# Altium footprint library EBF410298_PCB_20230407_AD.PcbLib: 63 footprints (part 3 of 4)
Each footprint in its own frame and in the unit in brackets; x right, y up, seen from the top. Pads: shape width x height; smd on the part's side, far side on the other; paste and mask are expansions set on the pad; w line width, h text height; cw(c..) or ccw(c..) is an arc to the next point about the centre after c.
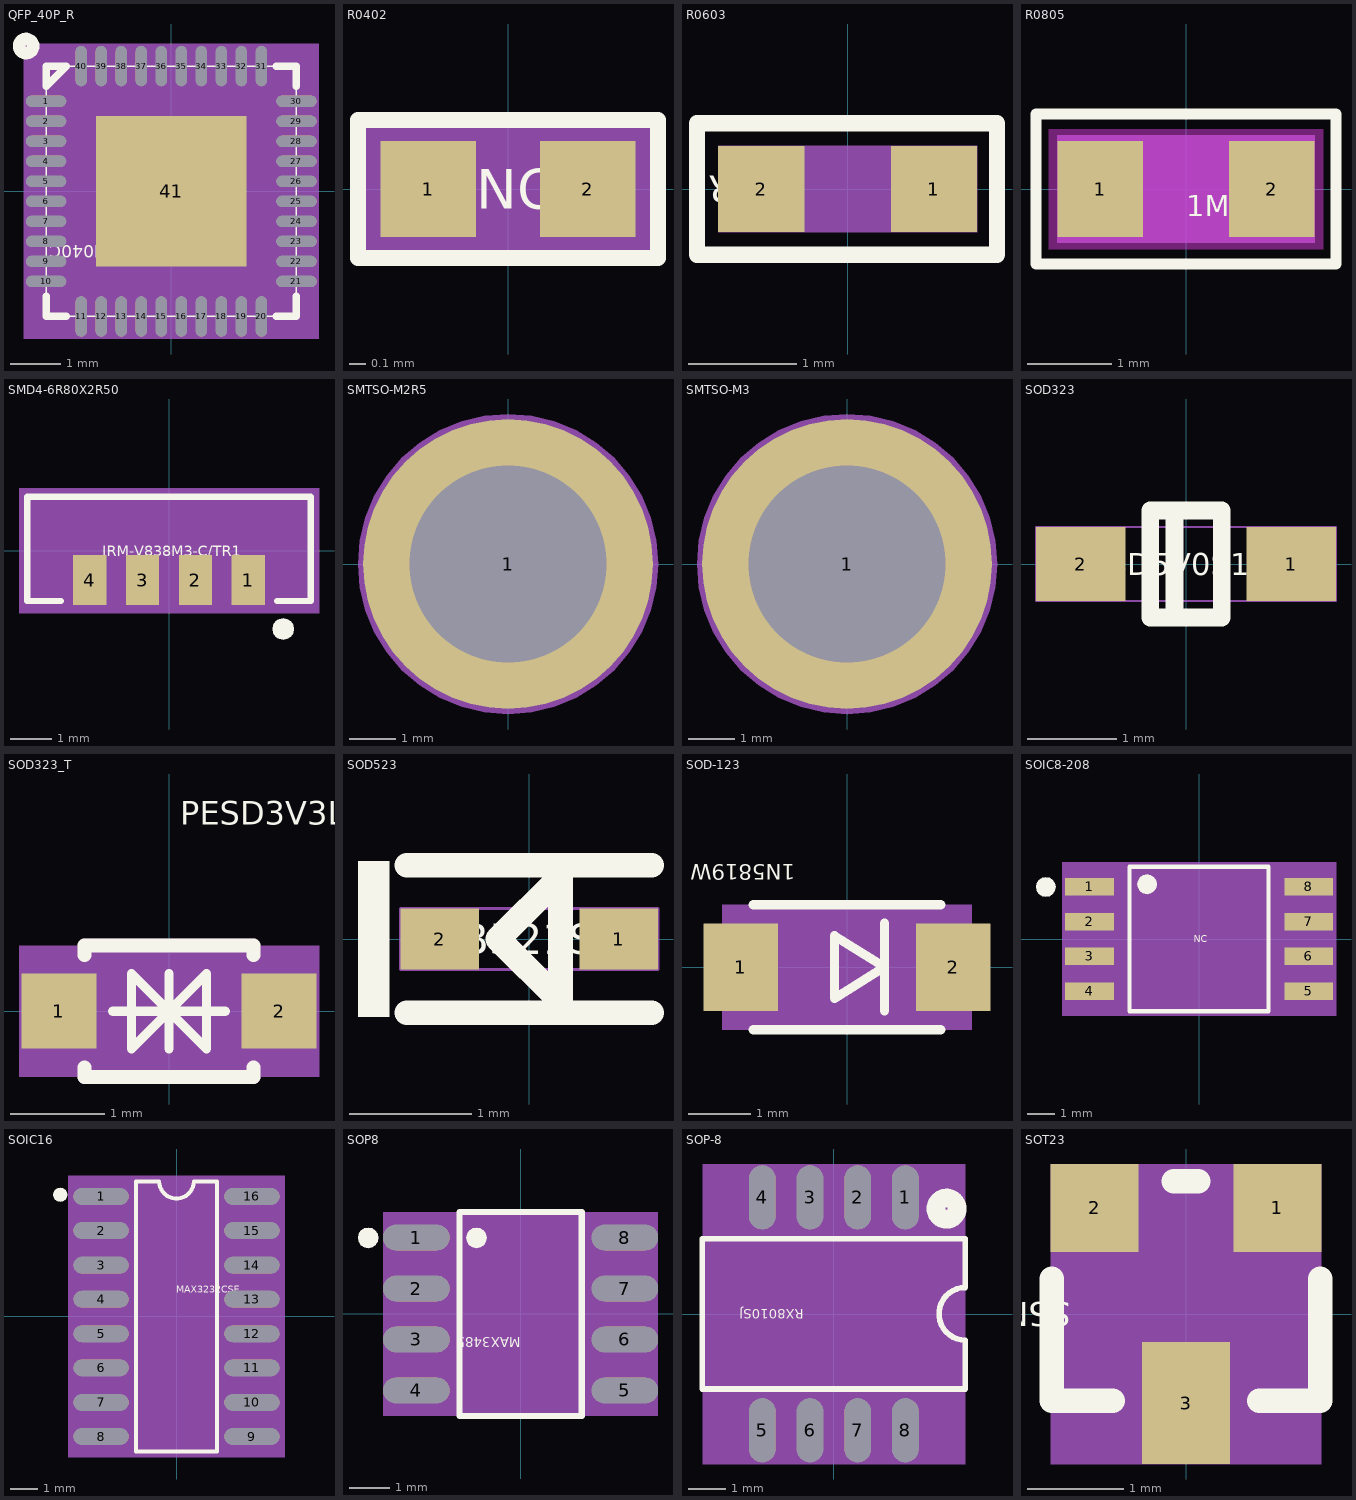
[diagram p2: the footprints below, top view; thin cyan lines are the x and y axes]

## QFP_40P_R [mil] "QFP_40P_R"
pads (41):
  oval 31.5x8.66 smd: 1(-98.43,70.87) 2(-98.43,55.12) 3(-98.43,39.37) 4(-98.43,23.62) 5(-98.43,7.87) 6(-98.43,-7.87) 7(-98.43,-23.62) 8(-98.43,-39.37) 9(-98.43,-55.12) 10(-98.43,-70.87) 21(98.43,-70.87) 22(98.43,-55.12) 23(98.43,-39.37) 24(98.43,-23.62) 25(98.43,-7.87) 26(98.43,7.87) 27(98.43,23.62) 28(98.43,39.37) 29(98.43,55.12) 30(98.43,70.87)
  oval 8.66x31.5 smd: 11(-70.87,-98.43) 12(-55.12,-98.43) 13(-39.37,-98.43) 14(-23.62,-98.43) 15(-7.87,-98.43) 16(7.87,-98.43) 17(23.62,-98.43) 18(39.37,-98.43) 19(55.12,-98.43) 20(70.87,-98.43) 31(70.87,98.43) 32(55.12,98.43) 33(39.37,98.43) 34(23.62,98.43) 35(7.87,98.43) 36(-7.87,98.43) 37(-23.62,98.43) 38(-39.37,98.43) 39(-55.12,98.43) 40(-70.87,98.43)
  rect 118.11x118.11 smd: 41(0,0)
Top Overlay:
  circle w9.84: c-114.17,114.17 r5.56
  lines w1: -98.43,-98.43 98.43,-98.43 98.43,98.43 -98.43,98.43 -98.43,-98.43
  lines w5.91: -98.43,-82.68 -98.43,-98.43 -82.68,-98.43 ; 82.68,-98.43 98.43,-98.43 98.43,-82.68 ; 82.68,98.43 98.43,98.43 98.43,82.68 ; -98.43,82.68 -98.43,98.43 -82.68,98.43 -98.43,82.68
  text "JL2101-N040C" at 0,-42.31 h9.84
Mechanical 5:
  dashed: -116.14,-116.14 116.14,-116.14 116.14,116.14 -116.14,116.14
Top 3D Body:
  region: -116.14,-116.14 116.14,-116.14 116.14,116.14 -116.14,116.14
Mechanical 17:
  text "12" at -55.12,-114.43 h20
  text "26" at 98.43,-8.13 h20
  text "27" at 98.43,7.62 h20
  text "22" at 98.43,-71.12 h20
  text "23" at 98.43,-55.37 h20
  text "24" at 98.43,-39.62 h20
  text "39" at -55.12,82.43 h20
  text "25" at 98.43,-23.87 h20
  text "40" at -70.87,82.43 h20
  text "11" at -70.87,-114.43 h20
  text "21" at 98.43,-86.87 h20
  text "8" at -98.43,-47.37 h20
  text "3" at -98.43,31.37 h20
  text "38" at -39.37,82.43 h20
  text "35" at 7.87,82.43 h20
  text "30" at 98.43,54.87 h20
  text "14" at -23.62,-114.43 h20
  text "20" at 70.87,-114.43 h20
  text "13" at -39.37,-114.43 h20
  text "34" at 23.62,82.43 h20
  text "33" at 39.37,82.43 h20
  text "10" at -98.43,-86.87 h20
  text "9" at -98.43,-63.12 h20
  text "7" at -98.43,-31.62 h20
  text "6" at -98.43,-15.87 h20
  text "5" at -98.43,-0.13 h20
  text "4" at -98.43,15.62 h20
  text "2" at -98.43,47.12 h20
  text "1" at -98.43,62.87 h20
  text "41" at 0,-16 h20
  text "32" at 55.12,82.43 h20
  text "29" at 98.43,39.12 h20
  text "37" at -23.62,82.43 h20
  text "36" at -7.87,82.43 h20
  text "31" at 70.87,82.43 h20
  text "19" at 55.12,-114.43 h20
  text "15" at -7.87,-114.43 h20
  text "16" at 7.87,-114.43 h20
  text "17" at 23.62,-114.43 h20
  text "18" at 39.37,-114.43 h20
  text "28" at 98.43,23.37 h20
Top Assembly:
  lines w1: -98.43,90.55 -90.55,98.43 ; -98.43,-98.43 98.43,-98.43 98.43,98.43 -98.43,98.43 -98.43,-98.43
  text ".Designator" at 0,-60 h50
3D body: height 150, standoff 0, extent -116.14,-116.14 116.14,116.14

## R0402 [mm] "R0402"
pads (2):
  rect 0.599x0.599 smd: 1(-0.5,0) 2(0.5,0)
Top Overlay:
  lines w0.102: -0.94,-0.432 0.94,-0.432 0.94,0.432 -0.94,0.432 -0.94,-0.432
  text "NC" at -0.2,-0.125 h0.25
Top 3D Body:
  region: 0.94,0.432 0.94,-0.432 -0.94,-0.432 -0.94,0.432
Mechanical 17:
  text "2" at 0.246,0 h0.64
  text "1" at -0.754,0 h0.64
Top Assembly:
  dashed: -0.94,-0.432 -0.94,0.432 0.94,0.432 0.94,-0.432
3D body: height 3.81, standoff 0, extent -0.94,-0.432 0.94,0.432

## R0603 [mil] "R0603"
pads (2):
  rect 31.5x31.5 smd: 1(31.5,0) 2(-31.5,0)
Top Overlay:
  lines w6: -55,-24 54.5,-24 54.5,24 -55,24 -55,-24
  text "510R" at -15.74,4.92 h9.84
Top 3D Body:
  region: 47.24,15.75 47.24,-15.75 -47.24,-15.75 -47.24,15.75
Mechanical 17:
  text "1" at 13.5,0 h45
  text "2" at -49.5,0 h45
3D body: height 150, standoff 0, extent -47.24,-15.75 47.24,15.75

## R0805 [mil] "R0805"
pads (2):
  rect 40x45 smd: 1(-40,0) 2(40,0)
Top Overlay:
  lines w5: -70,-35 70,-35 70,35 -70,35 -70,-35
  text "1M" at 0.01,-12.79 h9.84
Top 3D Body:
  region: -60,25 60,25 60,-25 -60,-25
Multi-Layer keep-out:
  region: -64,-28 -64,28 64,28 64,-28
Mechanical 17:
  text "1" at -40,-12 h30
  text "2" at 40,-12 h30
Top Assembly:
  text "R0805" at -115,45 h25
3D body: height 150, standoff 0, extent -60,-25 60,25

## SMD4-6R80X2R50 [mm] "SMD4-6R80X2R50"
pads (4):
  rect 0.8x1.2 smd: 1(1.905,-0.7) 2(0.635,-0.7) 3(-0.635,-0.7) 4(-1.905,-0.7)
Top Overlay:
  dashed: 2.996,-1.875 2.976,-1.777 2.921,-1.695 2.839,-1.639 2.741,-1.62 2.643,-1.639 2.616,-1.658 2.561,-1.695 2.505,-1.777 2.486,-1.875 2.505,-1.973 2.561,-2.055 2.616,-2.092 2.643,-2.111 2.741,-2.13 2.839,-2.111 2.921,-2.055 2.976,-1.973
  lines w0.15: -2.6,-1.2 -3.4,-1.2 -3.4,1.3 3.4,1.3 3.4,-1.2 2.6,-1.2
  text "IRM-V838M3-C/TR1" at -1.599,-0.125 h0.25
Top 3D Body:
  region: -3.6,1.5 -3.6,-1.5 3.6,-1.5 3.6,1.5
Mechanical 17:
  text "4" at -2.159,-0.7 h0.64
  text "1" at 1.651,-0.7 h0.64
  text "2" at 0.381,-0.7 h0.64
  text "3" at -0.889,-0.7 h0.64
Top Assembly:
  lines w0.15: -3.4,-1.2 3.4,-1.2 3.4,1.3 -3.4,1.3 -3.4,-1.2
3D body: height 3.81, standoff 0, extent -3.6,-1.5 3.6,1.5

## SMTSO-M2R5 [mm] "SMTSO-M2R5"
pads (1):
  round 6.2 / inner round 5.2 / far side round 5.2 hole 4.22: 1(0,0)
Top Overlay:
  text "M2.5X3mm" at -0.8,-0.125 h0.25
Top 3D Body:
  region: 3.21,0 3.17,0.502 3.053,0.992 2.86,1.457 2.597,1.887 2.27,2.27 1.887,2.597 1.457,2.86 0.992,3.053 0.502,3.17 0,3.21 -0.502,3.17 -0.992,3.053 -1.457,2.86 -1.601,2.772 -1.887,2.597 -2.27,2.27 -2.597,1.887 -2.86,1.457 -3.053,0.992 -3.17,0.502 -3.21,0 -3.17,-0.502 -3.053,-0.992 -2.86,-1.457 -2.597,-1.887 -2.27,-2.27 -1.887,-2.597 -1.601,-2.772 -1.457,-2.86 -0.992,-3.053 -0.502,-3.17 0,-3.21 0.502,-3.17 0.992,-3.053 1.457,-2.86 1.887,-2.597 2.27,-2.27 2.597,-1.887 2.86,-1.457 3.053,-0.992 3.17,-0.502
Mechanical 17:
  text "1" at -0.254,0 h0.64
3D body: height 3.81, standoff 0, extent -3.21,-3.21 3.21,3.21

## SMTSO-M3 [mm] "SMTSO-M3"
pads (1):
  round 6.2 / inner round 5.2 / far side round 5.2 hole 4.22: 1(0,0)
Top Overlay:
  text "M3X3.5mm" at -0.8,-0.125 h0.25
Top 3D Body:
  region: 3.21,0 3.17,0.502 3.053,0.992 2.86,1.457 2.597,1.887 2.27,2.27 1.887,2.597 1.457,2.86 0.992,3.053 0.502,3.17 0,3.21 -0.502,3.17 -0.992,3.053 -1.457,2.86 -1.601,2.772 -1.887,2.597 -2.27,2.27 -2.597,1.887 -2.86,1.457 -3.053,0.992 -3.17,0.502 -3.21,0 -3.17,-0.502 -3.053,-0.992 -2.86,-1.457 -2.597,-1.887 -2.27,-2.27 -1.887,-2.597 -1.601,-2.772 -1.457,-2.86 -0.992,-3.053 -0.502,-3.17 0,-3.21 0.502,-3.17 0.992,-3.053 1.457,-2.86 1.887,-2.597 2.27,-2.27 2.597,-1.887 2.86,-1.457 3.053,-0.992 3.17,-0.502
Mechanical 17:
  text "1" at -0.376,0 h0.94
3D body: height 3.81, standoff 0, extent -3.21,-3.21 3.21,3.21

## SOD323 [mm] "SOD323"
pads (2):
  rect 1x0.83 smd: 1(1.18,0) 2(-1.18,0)
Top Overlay:
  lines w0.2: -0.13,-0.6 -0.13,0.6 ; -0.4,-0.6 0.4,-0.6 0.4,0.6 -0.4,0.6 -0.4,-0.6
  text "PESD5V0S1BA-N" at -1.3,-0.125 h0.25
Top 3D Body:
  lines w0.025: -1.68,-0.415 -1.68,0.415 1.68,0.415 1.68,-0.415 -1.68,-0.415
Mechanical 17:
  text "2" at -1.302,0 h0.3
  text "1" at 1.058,0 h0.3

## SOD323_T [mm] "SOD323_T"
pads (2):
  rect 0.8x0.8 smd: 1(-1.175,0) 2(1.175,0)
Top Overlay:
  lines w0.1: -0.6,0 0.6,0 ; 0,-0.4 0,0.4 ; 0,0 -0.4,-0.4 -0.4,0.4 0,0 ; 0,0 0.4,0.4 0.4,-0.4 0,0
  lines w0.15: -0.9,-0.6 -0.9,-0.7 0.9,-0.7 0.9,-0.6 ; -0.9,0.6 -0.9,0.7 0.9,0.7 0.9,0.6
  text "PESD3V3L1BA" at 0.122,1.991 h0.25
Top 3D Body:
  region: -1.6,0.7 -1.6,-0.7 1.6,-0.7 1.6,0.7
Mechanical 17:
  text "2" at 1.175,0.254 h0.64
  text "1" at -1.175,0.254 h0.64
Top Assembly:
  lines w0.15: -0.9,-0.7 0.9,-0.7 0.9,0.7 -0.9,0.7 -0.9,-0.7
3D body: height 3.81, standoff 0, extent -1.6,-0.7 1.6,0.7

## SOD523 [mm] "SOD523"
pads (2):
  rect 0.64x0.5 smd: 1(0.73,0) 2(-0.73,0)
Top Overlay:
  dashed: -1.397,0.635 -1.397,-0.635 -1.143,-0.635 -1.143,0.635
  lines w0.2: -1,-0.6 1,-0.6 ; -1,0.6 1,0.6
  lines w0.203: -0.254,0 0.254,0.508 0.254,-0.508 -0.254,0
  text "RB521S30" at -0.8,-0.125 h0.25
Top 3D Body:
  lines w0.025: -1.05,-0.25 1.05,-0.25 1.05,0.25 -1.05,0.25 -1.05,-0.25
Mechanical 17:
  text "1" at 0.273,0 h1.14
  text "2" at -1.187,0 h1.14

## SOD-123 [mm] "SOD-123"
pads (2):
  rect 1.2x1.4 smd: 1(-1.7,0) 2(1.7,0)
Top Overlay:
  lines w0.15: -1.5,-1 1.5,-1 ; -1.5,1 1.5,1 ; 0.6,-0.7 0.6,0.7 ; -0.2,-0.5 -0.2,0.5 0.6,0 -0.2,-0.5
  text "1N5819W" at -0.827,1.649 h0.25
Top 3D Body:
  region: -2,-1 -2,1 2,1 2,-1
Mechanical 17:
  text "2" at 1.385,0 h0.79
  text "1" at -2.015,0 h0.79
3D body: height 3.81, standoff 0, extent -2,-1 2,1

## SOIC8-208 [mm] "SOIC8-208"
pads (8):
  rect 1.778x0.635 smd: 1(-4,1.905) 2(-4,0.635) 3(-4,-0.635) 4(-4,-1.905) 5(4,-1.905) 6(4,-0.635) 7(4,0.635) 8(4,1.905)
Top Overlay:
  dashed: -5.243,1.9 -5.27,2.037 -5.348,2.152 -5.463,2.23 -5.6,2.257 -5.737,2.23 -5.775,2.204 -5.852,2.152 -5.93,2.037 -5.957,1.9 -5.93,1.763 -5.852,1.648 -5.775,1.596 -5.737,1.57 -5.6,1.543 -5.463,1.57 -5.348,1.648 -5.27,1.763
  dashed: -1.543,2 -1.57,2.137 -1.648,2.252 -1.763,2.33 -1.9,2.357 -2.037,2.33 -2.075,2.304 -2.152,2.252 -2.23,2.137 -2.257,2 -2.23,1.863 -2.152,1.748 -2.075,1.696 -2.037,1.67 -1.9,1.643 -1.763,1.67 -1.648,1.748 -1.57,1.863
  lines w0.152: -2.54,-2.64 2.54,-2.64 2.54,2.64 -2.54,2.64 -2.54,-2.64
  text "NC" at -0.2,-0.125 h0.25
Top 3D Body:
  region: -5,2.8 -5,-2.8 5,-2.8 5,2.8
Mechanical 17:
  text "4" at -4.203,-1.905 h0.51
  text "8" at 3.797,1.905 h0.51
  text "7" at 3.797,0.635 h0.51
  text "5" at 3.797,-1.905 h0.51
  text "2" at -4.203,0.635 h0.51
  text "1" at -4.203,1.905 h0.51
  text "6" at 3.797,-0.635 h0.51
  text "3" at -4.203,-0.635 h0.51
Top Assembly:
  lines w0.152: -2.54,-2.64 2.54,-2.64 2.54,2.64 -2.54,2.64 -2.54,-2.64
3D body: height 3.81, standoff 0, extent -5,-2.8 5,2.8

## SOIC16 [mil] "SOIC16"
pads (16):
  oval 80x24 smd: 1(-109.8,174.8) 2(-109.8,125.2) 3(-109.8,74.8) 4(-109.8,25.2) 5(-109.8,-25.2) 6(-109.8,-74.8) 7(-109.8,-125.2) 8(-109.8,-174.8) 9(109.8,-174.8) 10(109.8,-125.2) 11(109.8,-74.8) 12(109.8,-25.2) 13(109.8,25.2) 14(109.8,74.8) 15(109.8,125.2) 16(109.8,174.8)
Top Overlay:
  dashed: -169.29,167.13 -165.45,167.89 -162.2,170.07 -160.02,173.32 -159.26,177.16 -160.02,181.01 -160.75,182.1 -162.2,184.26 -165.45,186.44 -169.29,187.2 -173.13,186.44 -176.39,184.26 -177.83,182.1 -178.56,181.01 -179.33,177.16 -178.56,173.32 -176.39,170.07 -173.13,167.89
  lines w5.91: -59.05,-196.85 -59.05,196.85 -39.37,196.85 -25.2,196.85 ccw(c0,196.85) 25.2,196.85 59.05,196.85 59.05,-196.85 -59.05,-196.85
  text "MAX3232CSE" at 0,34.44 h9.84
Top 3D Body:
  region: -157.48,204.72 -157.48,-204.72 157.48,-204.72 157.48,204.72
Mechanical 17:
  text "16" at 109.8,184.4 h12
  text "4" at -109.8,30 h12
  text "5" at -109.8,-20.4 h12
  text "2" at -109.8,130 h12
  text "6" at -109.8,-70 h12
  text "1" at -109.8,179.6 h12
  text "3" at -109.8,79.6 h12
  text "15" at 109.8,134.8 h12
  text "9" at 109.8,-170 h12
  text "10" at 109.8,-115.6 h12
  text "11" at 109.8,-65.2 h12
  text "12" at 109.8,-15.6 h12
  text "14" at 109.8,84.4 h12
  text "13" at 109.8,34.8 h12
  text "7" at -109.8,-120.4 h12
  text "8" at -109.8,-170 h12
3D body: height 150, standoff 0, extent -157.48,-204.72 157.48,204.72

## SOP8 [mil] "SOP8"
pads (8):
  oval 65x25 smd: 1(-102.36,75) 2(-102.36,25) 3(-102.36,-25) 4(-102.36,-75) 5(102.36,-75) 6(102.36,-25) 7(102.36,25) 8(102.36,75)
Top Overlay:
  dashed: -149.61,84.84 -153.45,84.07 -156.7,81.9 -158.88,78.64 -159.64,74.8 -158.88,70.96 -158.15,69.87 -156.7,67.71 -153.45,65.53 -149.61,64.77 -145.77,65.53 -142.51,67.71 -141.06,69.87 -140.34,70.96 -139.57,74.8 -140.34,78.64 -142.51,81.9 -145.77,84.07
  dashed: -43.31,84.84 -47.15,84.07 -50.4,81.9 -52.58,78.64 -53.34,74.8 -52.58,70.96 -51.85,69.87 -50.4,67.71 -47.15,65.53 -43.31,64.77 -39.47,65.53 -36.21,67.71 -34.77,69.87 -34.04,70.96 -33.27,74.8 -34.04,78.64 -36.21,81.9 -39.47,84.07
  lines w6: -60,-100 -60,100 60,100 60,-100 -60,-100
  text "MAX3485" at 0,-22.63 h9.84
Top 3D Body:
  region: -134.86,-100 134.86,-100 134.86,100 -134.86,100
Mechanical 17:
  text "4" at -102.36,-85 h25
  text "1" at -102.36,65 h25
  text "2" at -102.36,15 h25
  text "3" at -102.36,-35 h25
  text "6" at 102.36,-35 h25
  text "7" at 102.36,15 h25
  text "5" at 102.36,-85 h25
  text "8" at 102.36,65 h25
3D body: height 150, standoff 0, extent -134.86,-100 134.86,100

## SOP-8 [mm] "SOP-8"
pads (8):
  oval 0.7x1.7 smd: 1(1.903,3.104) 2(0.633,3.104) 3(-0.637,3.104) 4(-1.907,3.104) 5(-1.907,-3.096) 6(-0.637,-3.096) 7(0.633,-3.096) 8(1.903,-3.096)
Top Overlay:
  circle w0.5: c2.998,2.804 r0.283
  lines w0.15: -3.502,-1.996 -3.502,2.004 3.498,2.004 3.498,0.704 ccw(c3.498,0.004) 3.498,-0.696 3.498,-1.996 -3.502,-1.996
  text "RX8010SJ" at -0.8,0.125 h0.25
Top 3D Body:
  region: -3.498,3.994 -3.498,-3.994 3.498,-3.994 3.498,3.994
Mechanical 17:
  text "4" at -2.079,3.104 h0.43
  text "5" at -2.079,-3.096 h0.43
  text "6" at -0.809,-3.096 h0.43
  text "7" at 0.461,-3.096 h0.43
  text "8" at 1.731,-3.096 h0.43
  text "2" at 0.461,3.104 h0.43
  text "1" at 1.731,3.104 h0.43
  text "3" at -0.809,3.104 h0.43
3D body: height 3.81, standoff 0, extent -3.498,-3.994 3.498,3.994

## SOT23 [mil] "SOT23"
pads (3):
  rect 36x36 smd: 1(37.5,43.5) 2(-37.5,43.5)
  rect 36x50 smd: 3(0,-36.5)
Top Overlay:
  lines w10: -55,14.5 -55,-35.5 -30,-35.5 ; -5,54.5 5,54.5 ; 30,-35.5 55,-35.5 55,14.5
  text "SSM3J328R-LF" at -47.23,4.92 h9.84
Top 3D Body:
  region: 55.5,61.5 55.5,-61.5 -55.5,-61.5 -55.5,61.5
Mechanical 17:
  text "3" at -18,-36.5 h45
  text "1" at 19.5,43.5 h45
  text "2" at -55.5,43.5 h45
3D body: height 150, standoff 0, extent -55.5,-61.5 55.5,61.5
